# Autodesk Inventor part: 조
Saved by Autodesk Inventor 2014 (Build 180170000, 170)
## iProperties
Created: 2025-02
Part Number: 조
Material: 일반
Document SubType Name: Modeling
Designer: dg
Density: 1 g/cm^3
Appearance: 기본값
Author: dg
Author: jhkim
Creation Date: 2025-02-05
Sending System: Autodesk Inventor 2025
Preprocessor: ST-DEVELOPER v20
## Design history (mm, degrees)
node "조1"
node "솔리드1"
node "기준1"
